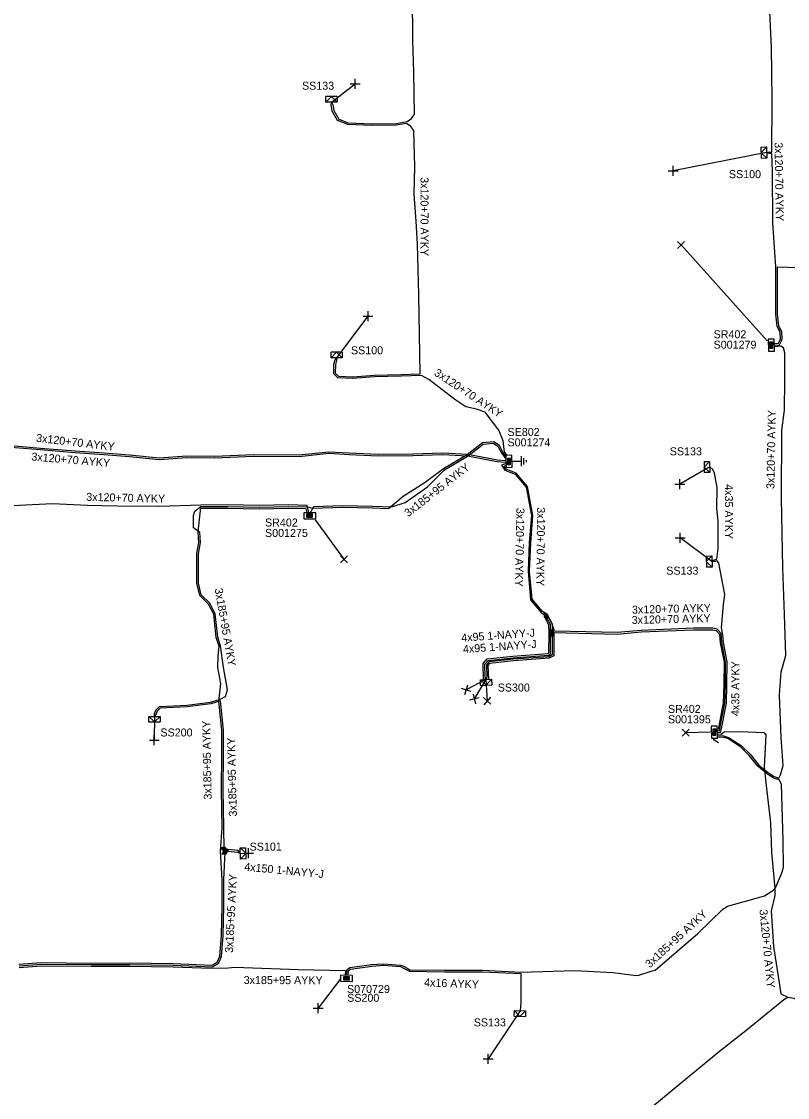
# Model space of a CAD drawing. Extents: x -763093 to -760976, y -1155572 to -1152009.
# Drawn here: x -762539.8 to -762444.1, y -1154689.2 to -1154554.8 of the extents above; entities that cross this region are included whole.
import ezdxf

# ---------------------------------------------------------------- set-up
doc = ezdxf.new("R2010")
doc.units = 0
for name, color, linetype in [('Vrstva 1', 7, 'Continuous'), ('Vrstva 14', 7, 'Continuous'), ('Vrstva 15', 7, 'Continuous'), ('Vrstva 19', 7, 'Continuous'), ('Vrstva 20', 7, 'Continuous'), ('Vrstva 28', 7, 'Continuous'), ('Vrstva 29', 7, 'Continuous'), ('Vrstva 30', 7, 'Continuous'), ('Vrstva 31', 7, 'Continuous'), ('Vrstva 33', 7, 'Continuous'), ('Vrstva 34', 7, 'Continuous'), ('Vrstva 4', 7, 'Continuous'), ('Vrstva 5', 7, 'Continuous'), ('Vrstva 59', 7, 'Continuous'), ('Vrstva 6', 7, 'Continuous'), ('Vrstva 8', 7, 'Continuous'), ('Vrstva 9', 7, 'Continuous')]:
    doc.layers.add(name, color=color, linetype=linetype)

# ---------------------------------------------------------------- blocks, each defined once
blk = doc.blocks.new('NN870')
at = {"layer": 'Vrstva 4'}
for points in [[(0, -0.25), (0.5, 0), (0, 0.25), (-0.5, 0), (0, -0.25)], [(0.37, 0), (0, 0.19), (-0.36, 0), (0, -0.19), (0.37, 0)], [(0.24, 0), (0, 0.12), (-0.25, 0), (0, -0.12), (0.24, 0)], [(0.12, 0), (0, 0.06), (-0.13, 0), (0, -0.06), (0.12, 0)]]:
    blk.add_lwpolyline(points, dxfattribs=at)
blk = doc.blocks.new('NN800')
at = {"layer": 'Vrstva 1'}
for points in [[(-0.44, 0.44), (0.44, -0.44)], [(-0.44, -0.44), (0.44, 0.44)]]:
    blk.add_lwpolyline(points, dxfattribs=at)
blk = doc.blocks.new('NN620')
at = {"layer": 'Vrstva 8'}
for points in [[(0.75, 0), (-0.75, 0)], [(-0.75, 0), (-0.75, -0.75)], [(0.75, -0.75), (0.75, 0)], [(-0.75, -0.75), (0.75, -0.75)], [(0.37, -0.18), (-0.38, -0.18)], [(-0.38, -0.18), (-0.38, -0.56)], [(-0.38, -0.56), (0.37, -0.56)], [(0.32, -0.23), (-0.33, -0.23)], [(-0.33, -0.23), (-0.33, -0.51)], [(-0.33, -0.51), (0.32, -0.51)], [(0.27, -0.27), (-0.28, -0.27)], [(-0.28, -0.27), (-0.28, -0.46)], [(-0.28, -0.46), (0.27, -0.46)], [(0.23, -0.32), (-0.23, -0.32)], [(-0.23, -0.32), (-0.23, -0.42)], [(-0.23, -0.42), (0.23, -0.42)], [(-0.19, -0.37), (0.19, -0.37)], [(0.23, -0.42), (0.23, -0.32)], [(0.27, -0.46), (0.27, -0.27)], [(0.32, -0.51), (0.32, -0.23)], [(0.37, -0.56), (0.37, -0.18)]]:
    blk.add_lwpolyline(points, dxfattribs=at)
blk = doc.blocks.new('NN630')
at = {"layer": 'Vrstva 9'}
for points in [[(0, -0.7), (-0.7, 0)], [(-0.7, -0.7), (-0.7, 0), (0.7, 0), (0.7, -0.7)], [(-0.7, -0.7), (0.7, -0.7)], [(0, -0.7), (0.7, 0)]]:
    blk.add_lwpolyline(points, dxfattribs=at)
blk = doc.blocks.new('NN810')
at = {"layer": 'Vrstva 14'}
for points in [[(0, -0.64), (0, -1.89)], [(0.63, -1.89), (-0.62, -1.89)], [(0.39, -2.2), (-0.4, -2.2)], [(0, -2.52), (-0.12, -2.52)], [(0.14, -2.52), (0, -2.52)]]:
    blk.add_lwpolyline(points, dxfattribs=at)

msp = doc.modelspace()

# ---------------------------------------------------------------- linework, layer by layer
at = {"layer": 'Vrstva 20'}
for points in [[(-762474.46, -1154629.16), (-762474.1, -1154628.97), (-762473.51, -1154630.08), (-762473.5, -1154631.23), (-762473.9, -1154631.23), (-762473.91, -1154630.18)], [(-762473.9, -1154631.23), (-762473.3, -1154631.23), (-762473.31, -1154634.07), (-762473.86, -1154634.36), (-762478.34, -1154634.69), (-762481.31, -1154635.02), (-762481.52, -1154635.25), (-762481.47, -1154637.01), (-762482.07, -1154637.03), (-762482.12, -1154635.03), (-762481.61, -1154634.45), (-762478.4, -1154634.09), (-762474.03, -1154633.77), (-762473.91, -1154633.71)]]:
    msp.add_lwpolyline(points, close=True, dxfattribs=at)
at = {"layer": 'Vrstva 5'}
for points in [[(-762445.71, -1154595.05), (-762445.25, -1154595.02), (-762445.07, -1154594.66), (-762444.99, -1154594.42), (-762445.02, -1154593.63), (-762445.3, -1154593.16), (-762445.42, -1154592.89), (-762445.58, -1154591.41), (-762445.59, -1154585.49), (-762445.94, -1154579.97), (-762446, -1154573.56), (-762446.06, -1154571.34), (-762446.4, -1154571.33), (-762446.73, -1154571.21), (-762446.39, -1154571.13), (-762446.06, -1154571.14), (-762446.04, -1154564.61), (-762446.11, -1154558.04), (-762446.44, -1154550.98), (-762446.8, -1154543.49), (-762446.96, -1154540.03), (-762447.45, -1154540.04)], [(-762479.18, -1154608.97), (-762479.44, -1154608.62), (-762479.64, -1154607.21), (-762480.16, -1154605.89), (-762481.85, -1154603.64), (-762482.95, -1154603.27), (-762484.3, -1154602.97), (-762485.66, -1154602.06), (-762488.92, -1154599.55), (-762489.83, -1154599.03), (-762492.35, -1154599.13), (-762495.68, -1154599.2), (-762498.41, -1154599.42), (-762500.25, -1154599.32), (-762500.78, -1154598.85), (-762500.75, -1154597.63), (-762500.6, -1154597.11), (-762500.41, -1154596.84), (-762500.43, -1154597.17), (-762500.55, -1154597.67), (-762500.58, -1154598.77), (-762500.17, -1154599.12), (-762498.41, -1154599.22), (-762495.7, -1154599), (-762492.35, -1154598.93), (-762489.99, -1154598.84), (-762490.09, -1154593.93), (-762490.15, -1154588.96), (-762490.3, -1154582.66), (-762490.49, -1154579.78), (-762490.73, -1154576.39), (-762490.67, -1154572.97), (-762490.76, -1154568.44), (-762491.16, -1154567.94), (-762491.71, -1154567.56), (-762492.97, -1154567.79), (-762496.01, -1154567.81), (-762499.01, -1154567.71), (-762500.29, -1154567.19), (-762500.98, -1154566.03), (-762501.11, -1154565.26), (-762501.06, -1154564.92), (-762500.9, -1154565.24), (-762500.78, -1154565.97), (-762500.15, -1154567.03), (-762498.97, -1154567.51), (-762496.01, -1154567.61), (-762492.99, -1154567.59), (-762491.63, -1154567.34), (-762491.08, -1154566.97), (-762490.69, -1154566.41), (-762490.79, -1154561.19), (-762490.92, -1154557.21), (-762490.96, -1154551.45)], [(-762445.7, -1154595.26), (-762445.12, -1154595.21), (-762444.89, -1154594.74), (-762444.79, -1154594.46), (-762444.82, -1154593.57), (-762445.12, -1154593.06), (-762445.22, -1154592.83), (-762445.38, -1154591.39), (-762445.39, -1154585.49), (-762441.65, -1154585.61)], [(-762452.82, -1154644), (-762452.13, -1154644.06), (-762451.47, -1154644.24), (-762449.89, -1154645.26), (-762448.78, -1154646.36), (-762447.7, -1154647.72), (-762446.62, -1154648.59), (-762445.77, -1154649.14), (-762445.19, -1154649.33), (-762444.99, -1154648.93), (-762444.74, -1154648.04), (-762444.65, -1154647.74), (-762444.91, -1154644.24), (-762445.12, -1154638.96), (-762444.91, -1154636.06), (-762444.35, -1154634.03), (-762444.48, -1154628.91), (-762444.69, -1154623.09), (-762444.86, -1154614.4), (-762444.82, -1154605.9), (-762444.54, -1154603.69), (-762444.48, -1154603.4), (-762444.47, -1154599.61), (-762444.44, -1154596.2), (-762444.61, -1154595.59), (-762444.94, -1154595.4), (-762445.7, -1154595.45)], [(-762541.57, -1154607.77), (-762537.41, -1154608.11), (-762533.06, -1154608.47), (-762529.46, -1154608.72), (-762526.28, -1154608.97), (-762522.56, -1154609.32), (-762519.14, -1154609.09), (-762515.62, -1154609.12), (-762510.78, -1154608.91), (-762505.11, -1154608.96), (-762501.39, -1154608.57), (-762498.85, -1154608.71), (-762495.22, -1154608.88), (-762490.89, -1154608.82), (-762487.19, -1154608.71), (-762484.05, -1154608.89), (-762480.34, -1154609.57), (-762479.31, -1154609.67)], [(-762514.47, -1154658.19), (-762514.49, -1154655.5), (-762514.59, -1154650.79), (-762514.54, -1154646.4), (-762514.55, -1154643.33), (-762514.92, -1154639.7), (-762516.12, -1154640.05), (-762519.09, -1154640.42), (-762522.44, -1154640.59), (-762522.83, -1154640.98), (-762522.95, -1154641.31), (-762523.17, -1154641.62), (-762523.16, -1154641.31), (-762523.01, -1154640.86), (-762522.52, -1154640.39), (-762519.11, -1154640.22), (-762516.16, -1154639.85), (-762515.06, -1154639.53), (-762514.3, -1154639.12), (-762514.05, -1154638.31), (-762514.54, -1154635.46), (-762514.92, -1154632.8), (-762515.27, -1154631.75), (-762515.57, -1154628.81), (-762516.26, -1154627.49), (-762517.32, -1154626.44), (-762517.68, -1154624.98), (-762517.66, -1154621.31), (-762517.41, -1154619.89), (-762517.5, -1154618.67), (-762518.28, -1154618.09), (-762518.3, -1154616.53), (-762518.11, -1154615.98), (-762517.37, -1154615.43), (-762514.01, -1154615.4), (-762510.1, -1154615.49), (-762506.42, -1154615.41), (-762504.11, -1154615.47), (-762503.34, -1154615.61), (-762499.7, -1154615.49), (-762495.92, -1154615.56), (-762493.94, -1154615.64), (-762492.11, -1154614.13), (-762489.37, -1154612.37), (-762487.06, -1154610.66), (-762484.13, -1154608.91), (-762482.21, -1154607.42), (-762480.8, -1154607.3), (-762480.12, -1154607.75), (-762479.62, -1154608.73), (-762479.29, -1154609.16)], [(-762503.66, -1154616.16), (-762503.27, -1154615.41), (-762499.7, -1154615.29), (-762495.92, -1154615.36), (-762493.54, -1154615.45), (-762491.88, -1154614.93), (-762489.06, -1154612.96), (-762486.96, -1154610.84), (-762484.01, -1154609.07), (-762482.13, -1154607.62), (-762480.86, -1154607.5), (-762480.28, -1154607.89), (-762479.8, -1154608.81), (-762479.3, -1154609.46)], [(-762541.59, -1154607.97), (-762537.43, -1154608.31), (-762533.08, -1154608.67), (-762529.48, -1154608.92), (-762526.3, -1154609.17), (-762522.56, -1154609.52), (-762519.14, -1154609.29), (-762515.62, -1154609.32), (-762510.78, -1154609.11), (-762505.11, -1154609.16), (-762501.39, -1154608.77), (-762498.87, -1154608.91), (-762495.22, -1154609.08), (-762490.89, -1154609.02), (-762487.19, -1154608.91), (-762484.09, -1154609.09), (-762480.36, -1154609.77), (-762479.34, -1154609.86)], [(-762479.32, -1154610.08), (-762479.82, -1154610.26), (-762479.4, -1154610.89), (-762478.13, -1154611.39), (-762476.77, -1154613), (-762476.1, -1154616.54), (-762476.37, -1154619.91), (-762476.52, -1154623.5), (-762476.22, -1154627.05), (-762474.86, -1154628.66), (-762474.28, -1154629.07)], [(-762452.82, -1154643.4), (-762452.63, -1154643.41), (-762452.51, -1154642.9), (-762451.95, -1154639.96), (-762451.88, -1154637.68), (-762451.85, -1154634.84), (-762452.33, -1154632.41), (-762452.42, -1154631.28), (-762452.92, -1154630.73), (-762453.43, -1154630.61), (-762455.87, -1154630.61), (-762462.4, -1154630.88), (-762465.4, -1154631.16), (-762473.2, -1154630.96), (-762473.5, -1154630.09), (-762474.1, -1154628.92), (-762474.7, -1154628.54), (-762476.02, -1154626.97), (-762476.32, -1154623.5), (-762476.17, -1154619.93), (-762475.9, -1154616.52), (-762476.59, -1154612.92), (-762478.01, -1154611.23), (-762479.26, -1154610.73), (-762479.51, -1154610.36), (-762479.32, -1154610.29)], [(-762452.83, -1154643.6), (-762452.47, -1154643.63), (-762452.31, -1154642.94), (-762451.75, -1154639.98), (-762451.68, -1154637.68), (-762451.65, -1154634.82), (-762452.13, -1154632.38), (-762452.21, -1154631.42), (-762452.35, -1154630.56), (-762452.1, -1154627.66), (-762451.96, -1154626.41), (-762452.71, -1154622.5), (-762452.89, -1154622.19), (-762453.21, -1154622.28), (-762453.56, -1154622.28), (-762453.26, -1154622.09), (-762452.93, -1154621.99), (-762452.79, -1154620.67), (-762452.78, -1154617.19), (-762452.94, -1154615.64), (-762452.89, -1154613.03), (-762453.25, -1154611.24), (-762453.46, -1154610.79), (-762453.83, -1154610.47)], [(-762503.87, -1154616.15), (-762504.09, -1154615.27), (-762506.42, -1154615.21), (-762510.1, -1154615.29), (-762514.01, -1154615.2), (-762517.37, -1154615.23), (-762522.56, -1154615.41), (-762527.8, -1154615.36), (-762531.54, -1154615.29), (-762535.89, -1154615.07), (-762540.05, -1154615.28), (-762544.02, -1154615.34), (-762546.63, -1154615.39), (-762546.79, -1154615.85)], [(-762540.08, -1154672.59), (-762537.32, -1154672.36), (-762531.07, -1154672.43), (-762526.22, -1154672.41), (-762520.81, -1154672.49), (-762515.97, -1154672.69), (-762515.33, -1154672.33), (-762514.99, -1154671.56), (-762514.78, -1154668.97), (-762514.72, -1154665.28), (-762514.7, -1154661.98), (-762514.9, -1154658.5), (-762514.69, -1154655.5), (-762514.79, -1154650.79), (-762514.74, -1154646.4), (-762514.75, -1154643.35), (-762515.12, -1154639.76), (-762514.86, -1154637.51), (-762515.25, -1154635.5), (-762515.2, -1154634.15), (-762515.1, -1154632.86), (-762515.47, -1154631.79), (-762515.77, -1154628.87), (-762516.42, -1154627.61), (-762517.5, -1154626.54), (-762517.88, -1154625), (-762517.86, -1154621.29), (-762517.61, -1154619.89), (-762517.71, -1154618.6), (-762517.45, -1154616.24), (-762517.39, -1154615.63), (-762514.01, -1154615.6), (-762510.1, -1154615.69), (-762506.42, -1154615.61), (-762504.25, -1154615.67), (-762504.12, -1154616.15)], [(-762473.5, -1154631.23), (-762473.51, -1154633.95), (-762473.92, -1154634.17), (-762478.36, -1154634.49), (-762481.41, -1154634.83), (-762481.72, -1154635.18), (-762481.68, -1154636.73), (-762481.77, -1154637.02), (-762481.88, -1154636.72), (-762481.92, -1154635.1), (-762481.51, -1154634.64), (-762478.38, -1154634.29), (-762473.98, -1154633.97), (-762473.71, -1154633.83), (-762473.7, -1154631.23), (-762473.71, -1154630.13), (-762474.28, -1154629.07)], [(-762473.5, -1154631.23), (-762473.32, -1154631.16), (-762465.4, -1154631.36), (-762462.38, -1154631.08), (-762455.87, -1154630.81), (-762453.45, -1154630.81), (-762453.02, -1154630.91), (-762452.62, -1154631.36), (-762452.53, -1154632.44), (-762452.05, -1154634.86), (-762452.08, -1154637.68), (-762452.15, -1154639.94), (-762452.71, -1154642.86), (-762452.78, -1154643.2), (-762452.85, -1154643.19)], [(-762452.82, -1154643.8), (-762452.42, -1154643.83), (-762452.01, -1154643.56), (-762450.06, -1154643.51), (-762447.09, -1154643.63), (-762446.81, -1154643.93), (-762447.05, -1154647.95), (-762446.75, -1154650.63), (-762446.26, -1154654.93), (-762446.1, -1154658.57), (-762445.72, -1154663.1), (-762445.72, -1154663.99), (-762446.17, -1154665.89), (-762445.86, -1154670.36), (-762445.33, -1154673.82), (-762444.96, -1154676.26), (-762444.09, -1154676.7), (-762443.32, -1154676.82), (-762441.48, -1154677.57)], [(-762499.18, -1154673.89), (-762499.11, -1154673.23), (-762498.78, -1154672.98), (-762496.06, -1154672.62), (-762494.56, -1154672.51), (-762492.41, -1154672.68), (-762492.07, -1154672.83), (-762491.54, -1154673.11), (-762491.26, -1154673.26), (-762486.94, -1154673.32), (-762482.21, -1154673.33), (-762477.4, -1154673.55), (-762470.69, -1154673.35), (-762465.95, -1154673.62), (-762463.3, -1154673.94), (-762462.8, -1154673.98), (-762461.02, -1154673.42), (-762460.65, -1154673.32), (-762455.3, -1154668.75), (-762452.21, -1154665.68), (-762451.62, -1154665.33), (-762448.16, -1154664.35), (-762446.99, -1154664.02), (-762445.95, -1154663.35), (-762445.56, -1154662.96), (-762444.78, -1154661.07), (-762444.63, -1154660.45), (-762444.66, -1154657.11), (-762444.85, -1154650.08), (-762445.16, -1154649.55), (-762445.85, -1154649.32), (-762446.74, -1154648.75), (-762447.84, -1154647.86), (-762448.92, -1154646.5), (-762450.01, -1154645.42), (-762451.57, -1154644.4), (-762452.17, -1154644.28), (-762452.81, -1154644.22)], [(-762453.39, -1154644.46), (-762452.72, -1154644.9)], [(-762540.06, -1154672.79), (-762537.31, -1154672.56), (-762531.07, -1154672.63), (-762526.22, -1154672.61), (-762520.82, -1154672.69), (-762515.93, -1154672.89), (-762515.17, -1154672.47), (-762514.79, -1154671.62), (-762514.58, -1154668.97), (-762514.52, -1154665.28), (-762514.5, -1154661.98), (-762514.35, -1154658.57)], [(-762514.35, -1154658.57), (-762514.02, -1154658.45), (-762512.78, -1154658.57), (-762512.43, -1154658.74), (-762512.7, -1154658.37), (-762514, -1154658.25), (-762514.47, -1154658.19)], [(-762540.04, -1154672.99), (-762537.3, -1154672.76), (-762531.07, -1154672.83), (-762526.22, -1154672.81), (-762520.83, -1154672.89), (-762516.13, -1154673.08), (-762513.98, -1154673.01), (-762513.12, -1154672.96), (-762505.22, -1154673.24), (-762499.32, -1154673.37), (-762499.37, -1154673.9)], [(-762498.97, -1154673.9), (-762498.92, -1154673.34), (-762498.7, -1154673.18), (-762496.04, -1154672.82), (-762494.56, -1154672.71), (-762492.45, -1154672.88), (-762492.15, -1154673.01), (-762491.64, -1154673.29), (-762491.32, -1154673.46), (-762486.94, -1154673.52), (-762482.21, -1154673.53), (-762477.4, -1154673.75), (-762477.41, -1154674.92), (-762477.41, -1154677.37), (-762477.52, -1154678.39)], [(-762462.15, -1154691.31), (-762457.55, -1154687.51), (-762452.6, -1154683.44), (-762449.12, -1154680.7), (-762444.57, -1154676.98), (-762444.09, -1154676.7)]]:
    msp.add_lwpolyline(points, dxfattribs=at)
at = {"layer": 'Vrstva 59'}
for points in [[(-762501.06, -1154564.92), (-762498.1, -1154562.63)], [(-762446.73, -1154571.21), (-762458.38, -1154573.5)], [(-762446.67, -1154594.72), (-762457.41, -1154582.75)], [(-762500.41, -1154596.84), (-762496.5, -1154591.63)], [(-762453.83, -1154610.47), (-762457.56, -1154612.63)], [(-762503.1, -1154617.07), (-762499.5, -1154622)], [(-762453.56, -1154622.28), (-762457.51, -1154619.33)], [(-762481.77, -1154637.02), (-762484.25, -1154638.32)], [(-762481.77, -1154637.02), (-762483.23, -1154639.44)], [(-762481.77, -1154637.02), (-762481.63, -1154639.7)], [(-762523.17, -1154641.62), (-762523.18, -1154644.58)], [(-762453.73, -1154643.6), (-762456.85, -1154643.67)], [(-762512.43, -1154658.74), (-762511.43, -1154658.72)], [(-762499.93, -1154674.41), (-762502.74, -1154678.05)], [(-762477.52, -1154678.39), (-762481.48, -1154684.38)]]:
    msp.add_lwpolyline(points, dxfattribs=at)

# ---------------------------------------------------------------- block references
at = {"layer": 'Vrstva 15', "rotation": 90.43101079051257}
msp.add_blockref('NN810', (-762479.27, -1154609.77), dxfattribs=at)
at = {"layer": 'Vrstva 19'}
for p, rotation in [((-762474.28, -1154629.07), -61.762554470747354), ((-762473.5, -1154631.23), -90.21539666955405), ((-762514.47, -1154658.19), -19.179008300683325), ((-762514.35, -1154658.57), 32.90524163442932)]:
    msp.add_blockref('NN870', p, dxfattribs=dict(at, rotation=rotation))
at = {"layer": 'Vrstva 28'}
for p, rotation in [((-762445.78, -1154595.26), -88.50897223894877), ((-762479.27, -1154609.77), 90.1813330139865), ((-762503.78, -1154616.19), -0.15476954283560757), ((-762452.89, -1154643.59), -88.86949441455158), ((-762499.18, -1154673.96), -1.2886444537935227)]:
    msp.add_blockref('NN620', p, dxfattribs=dict(at, rotation=rotation))
at = {"layer": 'Vrstva 31'}
for p, rotation in [((-762501.06, -1154564.92), 179.67216948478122), ((-762446.73, -1154571.21), -88.50897224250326), ((-762500.41, -1154596.84), -179.52096115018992), ((-762453.83, -1154610.47), -88.91321942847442), ((-762453.56, -1154622.28), -88.86236113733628), ((-762481.77, -1154637.02), 2.5492404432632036), ((-762523.17, -1154641.62), 0.07877505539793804), ((-762512.43, -1154658.74), 91.1536055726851), ((-762477.52, -1154678.39), -1.1962944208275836)]:
    msp.add_blockref('NN630', p, dxfattribs=dict(at, rotation=rotation))
at = {"layer": 'Vrstva 34'}
for p, rotation in [((-762498.1, -1154562.63), 45), ((-762458.38, -1154573.5), 45), ((-762496.5, -1154591.63), 45), ((-762457.56, -1154612.63), 45), ((-762457.51, -1154619.33), 45.00000009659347), ((-762484.25, -1154638.32), -152.21643096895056), ((-762483.23, -1154639.44), -121.02381817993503), ((-762481.63, -1154639.7), -87.07719079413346), ((-762523.18, -1154644.58), 45), ((-762511.43, -1154658.72), 45), ((-762502.74, -1154678.05), 45), ((-762481.48, -1154684.38), 45)]:
    msp.add_blockref('NN800', p, dxfattribs=dict(at, rotation=rotation))
for p in [(-762457.41, -1154582.75), (-762499.5, -1154622), (-762456.85, -1154643.67)]:
    msp.add_blockref('NN800', p, dxfattribs=at)

# ---------------------------------------------------------------- texts
at = {"layer": 'Vrstva 29'}
for s, p in [('S001279', (-762453.35, -1154595.7)), ('S001274', (-762479.08, -1154607.9)), ('S001275', (-762509.36, -1154619.21)), ('S001395', (-762459.05, -1154642.49)), ('S070729', (-762499.12, -1154676.17))]:
    msp.add_text(s, height=1, dxfattribs=at).set_placement(p)
at = {"layer": 'Vrstva 30'}
for s, p in [('SR402', (-762453.35, -1154594.4)), ('SE802', (-762479.08, -1154606.6)), ('SR402', (-762509.36, -1154617.91)), ('SR402', (-762459.05, -1154641.19)), ('SS200', (-762499.1, -1154677.27))]:
    msp.add_text(s, height=1, dxfattribs=at).set_placement(p)
at = {"layer": 'Vrstva 33'}
for s, p in [('SS133', (-762504.74, -1154563.36)), ('SS100', (-762451.44, -1154574.4)), ('SS100', (-762498.63, -1154596.4)), ('SS133', (-762458.82, -1154609.02)), ('SS133', (-762459.26, -1154623.92)), ('SS300', (-762480.31, -1154638.52)), ('SS200', (-762522.42, -1154644.13)), ('SS101', (-762511.28, -1154658.39)), ('SS133', (-762483.3, -1154680.34))]:
    msp.add_text(s, height=1, dxfattribs=at).set_placement(p)
at = {"layer": 'Vrstva 6'}
for s, rotation, p in [('3x120+70 AYKY', 270.957, (-762445.74, -1154569.93)), ('3x120+70 AYKY', 269.964, (-762489.94, -1154574.28)), ('3x120+70 AYKY', 326.603, (-762488.34, -1154598.95)), ('3x120+70 AYKY', 88.953, (-762445.76, -1154613.24)), ('3x120+70 AYKY', 353.463, (-762537.98, -1154607.32)), ('3x120+70 AYKY', 355.257, (-762538.56, -1154609.66)), ('3x185+95 AYKY', 37.979, (-762491.48, -1154616.76)), ('4x35 AYKY', 270.171, (-762451.94, -1154612.63)), ('3x120+70 AYKY', 358.605, (-762531.69, -1154614.7)), ('3x120+70 AYKY', 268.869, (-762477.96, -1154615.57)), ('3x120+70 AYKY', 269.421, (-762475.39, -1154615.5)), ('3x185+95 AYKY', 279.953, (-762515.65, -1154625.7)), ('3x120+70 AYKY', 1.409, (-762463.53, -1154628.8)), ('3x120+70 AYKY', 1.41, (-762463.56, -1154630.09)), ('4x95 1-NAYY-J', 4.141, (-762484.82, -1154632.31)), ('4x95 1-NAYY-J', 4.141, (-762484.61, -1154633.73)), ('4x35 AYKY', 89.826, (-762450.14, -1154641.59)), ('3x185+95 AYKY', 91.154, (-762516.01, -1154652.01)), ('3x185+95 AYKY', 91.386, (-762512.87, -1154654.12)), ('4x150 1-NAYY-J', 354.601, (-762511.98, -1154660.88)), ('3x185+95 AYKY', 87.044, (-762513.37, -1154671.18)), ('3x185+95 AYKY', 42.541, (-762461.33, -1154673.1)), ('3x120+70 AYKY', 275.596, (-762447.63, -1154665.78)), ('3x185+95 AYKY', 359.851, (-762512.02, -1154675.05)), ('4x16 AYKY', 357.698, (-762489.51, -1154675.33))]:
    msp.add_text(s, height=1, rotation=rotation, dxfattribs=at).set_placement(p)

doc.saveas('drawing.dxf')
